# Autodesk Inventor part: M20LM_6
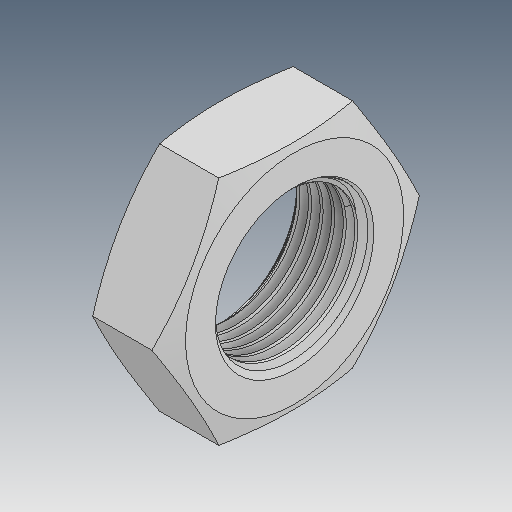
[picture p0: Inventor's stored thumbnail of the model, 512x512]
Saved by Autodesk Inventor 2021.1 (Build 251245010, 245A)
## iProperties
Created: 2019-04
Part Number: M20LM_6
Material: Ogólny
Document SubType Name: Modeling
Designer: user
Density: 1 g/cm^3
Appearance: Domyślna
Author: user
Revision Number: ÈÎºÎ
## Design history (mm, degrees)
feature "ÊäÈë1"
node "Bryła1"
